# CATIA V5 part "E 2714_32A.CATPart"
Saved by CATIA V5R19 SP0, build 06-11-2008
Definition: E 2714_32A
Nomenclature: E 2714_32A
Description: PART--DESC
Material "Aluminium": density 2710 kg/m3, Young's modulus 7e+10 Pa, Poisson ratio 0.346, thermal expansion 2.36e-05 1/K
Bounding box of the stored display mesh (mm): x -51 to 51, y -56.5 to 35, z -15.8 to 87
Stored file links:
  G:\UTB\Kombinované\Bakalářská práce\Catia\FORMA\E 2714_32A.CATPart
  D:\Aplikace\CATIA\Nová složka\win_b64\startup\materials\Catalog.CATMaterial
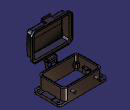
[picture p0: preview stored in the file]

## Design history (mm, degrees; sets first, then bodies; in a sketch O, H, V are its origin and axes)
Body1 "E 2714_32A" (main body)
  Solid1: solid without history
